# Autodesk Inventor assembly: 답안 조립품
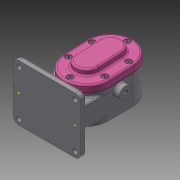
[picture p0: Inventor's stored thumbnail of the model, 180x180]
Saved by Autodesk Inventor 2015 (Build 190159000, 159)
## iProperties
Created: 2020-09
Part Number: 답안 조립품
Document SubType Name: Assembly
Designer: Administrator
Author: Administrator
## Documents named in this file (11)
- C:\Users\Administrator.SC-201903281308\Desktop\700906v1032\답안 조립품.iam
- C:\Users\Administrator.SC-201903281308\Desktop\700906v1032\본체.ipt
- C:\Users\Administrator.SC-201903281308\Desktop\700906v1032\메인축.ipt
- C:\Users\Administrator.SC-201903281308\Desktop\700906v1032\베어링부시.ipt
- C:\Users\Administrator.SC-201903281308\Desktop\700906v1032\스퍼기어.ipt
- C:\Users\Administrator.SC-201903281308\Desktop\700906v1032\키 6 x 6 x 18.ipt
- C:\Users\Administrator.SC-201903281308\Desktop\700906v1032\오일 실 16 28 7.ipt
- C:\Users\Administrator.SC-201903281308\Desktop\700906v1032\커버.ipt
- C:\Users\Administrator.SC-201903281308\Desktop\700906v1032\서브축.ipt
- C:\Users\Administrator.SC-201903281308\Desktop\700906v1032\개스킷.ipt
- C:\Users\Administrator.SC-201903281308\Desktop\700906v1032\볼트 M5.ipt
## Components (1 placed, 1 different names)
1. 개스킷:1
